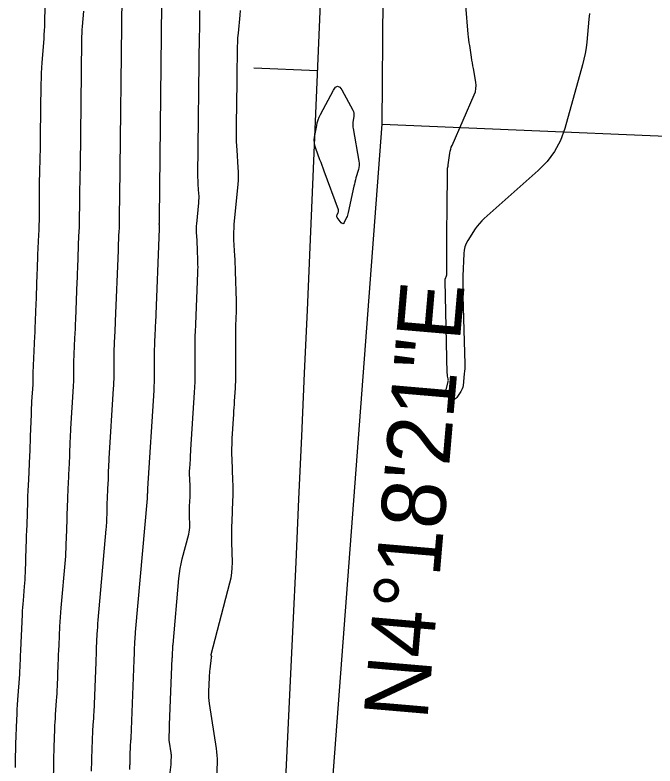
# Model space of a CAD drawing. Extents: x 1768942 to 1774819, y 723037 to 732099.
# Drawn here: x 1770550.2 to 1770610.2, y 730924.2 to 730994.7 of the extents above; entities that cross this region are included whole.
import ezdxf

# ---------------------------------------------------------------- set-up
doc = ezdxf.new("R2010")
doc.units = 0
for name, color, linetype in [('R_Contours', 7, 'Continuous'), ('R_Horz Alg', 7, 'Continuous'), ('R_Horz Alg Annot', 7, 'Continuous')]:
    doc.layers.add(name, color=color, linetype=linetype)

msp = doc.modelspace()

# ---------------------------------------------------------------- linework, layer by layer
at = {"layer": 'R_Contours'}
for points in [[(1770560.925, 730923.896), (1770560.946, 730924.309), (1770560.95, 730924.406), (1770560.954, 730924.503), (1770560.957, 730924.6), (1770560.959, 730924.697), (1770560.967, 730925.09), (1770560.969, 730925.184), (1770560.971, 730925.279), (1770560.974, 730925.373), (1770560.977, 730925.467), (1770560.991, 730925.872), (1770560.994, 730925.952), (1770560.998, 730926.032), (1770561.003, 730926.112), (1770561.008, 730926.192), (1770561.031, 730926.513), (1770561.036, 730926.593), (1770561.041, 730926.673), (1770561.045, 730926.753), (1770561.048, 730926.833), (1770561.339, 730934.168), (1770561.348, 730934.387), (1770561.357, 730934.606), (1770561.366, 730934.825), (1770561.376, 730935.044), (1770561.416, 730935.919), (1770561.427, 730936.138), (1770561.441, 730936.357), (1770561.456, 730936.575), (1770561.474, 730936.794), (1770562.586, 730949.35), (1770562.589, 730949.376), (1770562.59, 730949.402), (1770562.592, 730949.428), (1770562.593, 730949.454), (1770562.603, 730949.773), (1770562.604, 730949.8), (1770562.605, 730949.826), (1770562.607, 730949.853), (1770562.608, 730949.88), (1770562.613, 730949.993), (1770562.614, 730950.016), (1770562.615, 730950.039), (1770562.616, 730950.062), (1770562.617, 730950.085), (1770562.62, 730950.176), (1770562.621, 730950.199), (1770562.622, 730950.222), (1770562.623, 730950.245), (1770562.625, 730950.268), (1770563.21, 730959.488), (1770563.231, 730959.879), (1770563.247, 730960.271), (1770563.256, 730960.663), (1770563.258, 730961.055), (1770563.255, 730962.92), (1770563.256, 730963.164), (1770563.26, 730963.407), (1770563.267, 730963.651), (1770563.276, 730963.895), (1770563.319, 730964.869), (1770563.329, 730965.112), (1770563.34, 730965.356), (1770563.35, 730965.599), (1770563.36, 730965.843), (1770563.712, 730974.656), (1770563.713, 730974.685), (1770563.714, 730974.715), (1770563.713, 730974.744), (1770563.713, 730974.773), (1770563.708, 730974.906), (1770563.707, 730974.928), (1770563.706, 730974.95), (1770563.705, 730974.971), (1770563.704, 730974.993), (1770563.699, 730975.08), (1770563.699, 730975.102), (1770563.699, 730975.124), (1770563.699, 730975.145), (1770563.701, 730975.167), (1770563.722, 730975.386), (1770563.724, 730975.41), (1770563.724, 730975.434), (1770563.724, 730975.458), (1770563.723, 730975.482), (1770563.716, 730975.577), (1770563.715, 730975.601), (1770563.714, 730975.625), (1770563.713, 730975.649), (1770563.713, 730975.673), (1770563.981, 730998.643)], [(1770557.342, 730923.739), (1770557.362, 730924.758), (1770557.368, 730925.002), (1770557.374, 730925.246), (1770557.381, 730925.49), (1770557.389, 730925.734), (1770557.425, 730926.783), (1770557.433, 730926.991), (1770557.443, 730927.198), (1770557.455, 730927.406), (1770557.469, 730927.613), (1770557.527, 730928.442), (1770557.541, 730928.65), (1770557.553, 730928.857), (1770557.564, 730929.065), (1770557.573, 730929.272), (1770557.76, 730933.986), (1770557.773, 730934.315), (1770557.787, 730934.644), (1770557.801, 730934.974), (1770557.816, 730935.303), (1770557.876, 730936.62), (1770557.892, 730936.949), (1770557.913, 730937.278), (1770557.937, 730937.607), (1770557.964, 730937.935), (1770558.719, 730946.465), (1770558.735, 730946.654), (1770558.747, 730946.842), (1770558.758, 730947.031), (1770558.765, 730947.22), (1770558.797, 730948.164), (1770558.816, 730948.731), (1770558.842, 730949.526), (1770558.849, 730949.718), (1770558.857, 730949.91), (1770558.865, 730950.102), (1770558.874, 730950.294), (1770558.914, 730951.115), (1770558.921, 730951.28), (1770558.928, 730951.445), (1770558.935, 730951.61), (1770558.941, 730951.776), (1770558.963, 730952.437), (1770558.969, 730952.602), (1770558.977, 730952.767), (1770558.985, 730952.932), (1770558.995, 730953.097), (1770559.412, 730959.669), (1770559.428, 730959.961), (1770559.44, 730960.253), (1770559.446, 730960.545), (1770559.448, 730960.837), (1770559.446, 730962.005), (1770559.448, 730962.297), (1770559.452, 730962.589), (1770559.46, 730962.881), (1770559.471, 730963.173), (1770559.535, 730964.629), (1770559.55, 730964.969), (1770559.565, 730965.309), (1770559.579, 730965.649), (1770559.593, 730965.989), (1770559.858, 730972.625), (1770559.863, 730972.763), (1770559.868, 730972.9), (1770559.873, 730973.038), (1770559.878, 730973.175), (1770559.895, 730973.726), (1770559.9, 730973.863), (1770559.906, 730974.001), (1770559.912, 730974.138), (1770559.918, 730974.276), (1770559.946, 730974.84), (1770559.952, 730974.98), (1770559.957, 730975.12), (1770559.96, 730975.26), (1770559.961, 730975.4), (1770559.962, 730976.002), (1770559.963, 730976.141), (1770559.964, 730976.279), (1770559.967, 730976.417), (1770559.97, 730976.556), (1770559.983, 730977.109), (1770559.986, 730977.248), (1770559.989, 730977.386), (1770559.991, 730977.525), (1770559.993, 730977.663), (1770560.223, 730996.458)], [(1770552.939, 730995.548), (1770552.915, 730994.022), (1770552.906, 730993.641), (1770552.891, 730993.26), (1770552.871, 730992.879), (1770552.844, 730992.499), (1770552.672, 730990.272), (1770552.638, 730989.774), (1770552.612, 730989.275), (1770552.594, 730988.776), (1770552.583, 730988.277), (1770552.523, 730983.358), (1770552.517, 730982.903), (1770552.509, 730982.448), (1770552.5, 730981.993), (1770552.49, 730981.538), (1770552.445, 730979.719), (1770552.436, 730979.264), (1770552.428, 730978.81), (1770552.423, 730978.355), (1770552.421, 730977.9), (1770552.417, 730975.92), (1770552.413, 730975.46), (1770552.404, 730975), (1770552.389, 730974.54), (1770552.369, 730974.081), (1770552.276, 730972.226), (1770552.255, 730971.774), (1770552.235, 730971.323), (1770552.218, 730970.871), (1770552.202, 730970.419), (1770552.135, 730968.33), (1770552.125, 730968.018), (1770552.114, 730967.707), (1770552.102, 730967.395), (1770552.09, 730967.084), (1770552.04, 730965.837), (1770552.028, 730965.526), (1770552.015, 730965.214), (1770552.001, 730964.903), (1770551.988, 730964.591), (1770551.836, 730961.138), (1770551.832, 730961.046), (1770551.83, 730960.953), (1770551.828, 730960.861), (1770551.828, 730960.769), (1770551.828, 730960.401), (1770551.828, 730960.309), (1770551.826, 730960.217), (1770551.822, 730960.125), (1770551.817, 730960.033), (1770551.716, 730958.447), (1770551.699, 730958.152), (1770551.683, 730957.857), (1770551.67, 730957.562), (1770551.659, 730957.266), (1770551.588, 730955.157), (1770551.572, 730954.707), (1770551.554, 730954.257), (1770551.535, 730953.807), (1770551.514, 730953.358), (1770551.406, 730951.121), (1770551.382, 730950.599), (1770551.359, 730950.076), (1770551.339, 730949.553), (1770551.32, 730949.03), (1770551.248, 730946.867), (1770551.231, 730946.353), (1770551.213, 730945.838), (1770551.196, 730945.324), (1770551.179, 730944.809), (1770551.098, 730942.375), (1770551.084, 730942.049), (1770551.067, 730941.723), (1770551.045, 730941.397), (1770551.018, 730941.072), (1770550.903, 730939.772), (1770550.876, 730939.446), (1770550.852, 730939.121), (1770550.832, 730938.795), (1770550.816, 730938.469), (1770550.662, 730935.095), (1770550.654, 730934.908), (1770550.646, 730934.721), (1770550.638, 730934.534), (1770550.631, 730934.347), (1770550.601, 730933.599), (1770550.593, 730933.413), (1770550.583, 730933.226), (1770550.572, 730933.039), (1770550.56, 730932.852), (1770550.39, 730930.454), (1770550.359, 730929.992), (1770550.333, 730929.53), (1770550.311, 730929.068), (1770550.293, 730928.605), (1770550.212, 730926.269), (1770550.195, 730925.725), (1770550.179, 730925.181), (1770550.165, 730924.638), (1770550.154, 730924.094)], [(1770556.571, 730995.085), (1770556.46, 730993.651), (1770556.438, 730993.331), (1770556.421, 730993.01), (1770556.41, 730992.689), (1770556.403, 730992.368), (1770556.258, 730980.51), (1770556.254, 730980.214), (1770556.249, 730979.917), (1770556.243, 730979.62), (1770556.237, 730979.324), (1770556.207, 730978.137), (1770556.201, 730977.841), (1770556.196, 730977.544), (1770556.193, 730977.248), (1770556.192, 730976.951), (1770556.189, 730975.66), (1770556.186, 730975.36), (1770556.18, 730975.06), (1770556.171, 730974.76), (1770556.157, 730974.46), (1770556.097, 730973.251), (1770556.083, 730972.956), (1770556.07, 730972.662), (1770556.059, 730972.367), (1770556.049, 730972.072), (1770556.011, 730970.893), (1770556.001, 730970.598), (1770555.991, 730970.304), (1770555.98, 730970.009), (1770555.968, 730969.714), (1770555.825, 730966.134), (1770555.808, 730965.698), (1770555.789, 730965.261), (1770555.771, 730964.825), (1770555.752, 730964.389), (1770555.653, 730962.155), (1770555.646, 730961.963), (1770555.641, 730961.771), (1770555.638, 730961.579), (1770555.637, 730961.387), (1770555.638, 730960.619), (1770555.637, 730960.427), (1770555.633, 730960.235), (1770555.625, 730960.043), (1770555.615, 730959.851), (1770555.365, 730955.926), (1770555.347, 730955.619), (1770555.331, 730955.312), (1770555.317, 730955.004), (1770555.306, 730954.697), (1770555.264, 730953.466), (1770555.253, 730953.159), (1770555.241, 730952.851), (1770555.228, 730952.544), (1770555.214, 730952.236), (1770555.14, 730950.707), (1770555.123, 730950.35), (1770555.108, 730949.993), (1770555.094, 730949.635), (1770555.081, 730949.278), (1770555.032, 730947.799), (1770555.02, 730947.448), (1770555.008, 730947.096), (1770554.997, 730946.744), (1770554.985, 730946.392), (1770554.938, 730944.986), (1770554.924, 730944.634), (1770554.905, 730944.283), (1770554.881, 730943.932), (1770554.852, 730943.581), (1770554.453, 730939.077), (1770554.417, 730938.638), (1770554.385, 730938.199), (1770554.358, 730937.76), (1770554.336, 730937.321), (1770554.256, 730935.562), (1770554.236, 730935.122), (1770554.217, 730934.683), (1770554.199, 730934.243), (1770554.181, 730933.803), (1770554.098, 730931.712), (1770554.083, 730931.377), (1770554.066, 730931.042), (1770554.046, 730930.707), (1770554.024, 730930.372), (1770553.929, 730929.034), (1770553.907, 730928.699), (1770553.888, 730928.364), (1770553.872, 730928.029), (1770553.859, 730927.694), (1770553.801, 730926.002), (1770553.788, 730925.608), (1770553.776, 730925.214), (1770553.766, 730924.82), (1770553.758, 730924.426), (1770553.726, 730922.781)], [(1770564.559, 730922.366), (1770564.797, 730924.381), (1770564.806, 730924.47), (1770564.814, 730924.56), (1770564.82, 730924.65), (1770564.823, 730924.74), (1770564.835, 730925.1), (1770564.835, 730925.19), (1770564.832, 730925.28), (1770564.824, 730925.37), (1770564.813, 730925.459), (1770564.653, 730926.487), (1770564.636, 730926.62), (1770564.625, 730926.754), (1770564.621, 730926.888), (1770564.624, 730927.022), (1770564.648, 730927.56), (1770564.653, 730927.694), (1770564.659, 730927.829), (1770564.665, 730927.963), (1770564.67, 730928.098), (1770564.918, 730934.351), (1770564.922, 730934.459), (1770564.927, 730934.568), (1770564.932, 730934.676), (1770564.936, 730934.785), (1770564.956, 730935.219), (1770564.962, 730935.327), (1770564.968, 730935.435), (1770564.976, 730935.544), (1770564.985, 730935.652), (1770565.533, 730941.837), (1770565.584, 730942.304), (1770565.655, 730942.767), (1770565.745, 730943.227), (1770565.854, 730943.683), (1770566.459, 730945.984), (1770566.507, 730946.198), (1770566.54, 730946.414), (1770566.557, 730946.632), (1770566.56, 730946.851), (1770566.539, 730947.733), (1770566.535, 730947.953), (1770566.535, 730948.174), (1770566.539, 730948.394), (1770566.546, 730948.614), (1770566.583, 730949.499), (1770566.59, 730949.719), (1770566.592, 730949.94), (1770566.59, 730950.161), (1770566.584, 730950.382), (1770566.549, 730951.28), (1770566.543, 730951.501), (1770566.543, 730951.722), (1770566.548, 730951.943), (1770566.558, 730952.164), (1770566.612, 730953.047), (1770566.625, 730953.268), (1770566.639, 730953.489), (1770566.652, 730953.709), (1770566.666, 730953.93), (1770567.007, 730959.306), (1770567.035, 730959.797), (1770567.054, 730960.289), (1770567.065, 730960.78), (1770567.068, 730961.273), (1770567.064, 730963.931), (1770567.065, 730964.078), (1770567.067, 730964.225), (1770567.071, 730964.373), (1770567.076, 730964.52), (1770567.102, 730965.109), (1770567.109, 730965.256), (1770567.115, 730965.403), (1770567.121, 730965.55), (1770567.127, 730965.698), (1770567.32, 730970.532), (1770567.329, 730970.796), (1770567.332, 730971.06), (1770567.33, 730971.324), (1770567.323, 730971.588), (1770567.282, 730972.782), (1770567.275, 730972.977), (1770567.267, 730973.173), (1770567.257, 730973.369), (1770567.247, 730973.565), (1770567.204, 730974.347), (1770567.197, 730974.543), (1770567.198, 730974.738), (1770567.205, 730974.933), (1770567.22, 730975.129), (1770567.406, 730977.096), (1770567.422, 730977.31), (1770567.429, 730977.525), (1770567.427, 730977.74), (1770567.417, 730977.954), (1770567.356, 730978.814), (1770567.343, 730979.029), (1770567.334, 730979.244), (1770567.33, 730979.459), (1770567.33, 730979.675), (1770567.485, 730992.917), (1770567.488, 730993.188), (1770567.491, 730993.459), (1770567.494, 730993.729), (1770567.497, 730994), (1770567.509, 730995.16)], [(1770569.107, 730923.234), (1770569.148, 730924.566), (1770569.151, 730924.898), (1770569.138, 730925.23), (1770569.11, 730925.56), (1770569.067, 730925.89), (1770568.412, 730930.113), (1770568.376, 730930.393), (1770568.354, 730930.674), (1770568.345, 730930.956), (1770568.351, 730931.238), (1770568.409, 730932.556), (1770568.419, 730932.746), (1770568.433, 730932.935), (1770568.45, 730933.125), (1770568.472, 730933.314), (1770568.606, 730934.425), (1770568.609, 730934.448), (1770568.611, 730934.47), (1770568.616, 730934.515), (1770568.616, 730934.526), (1770568.615, 730934.537), (1770568.612, 730934.548), (1770568.608, 730934.558), (1770568.573, 730934.635), (1770568.567, 730934.651), (1770568.564, 730934.668), (1770568.565, 730934.685), (1770568.568, 730934.702), (1770570.332, 730941.421), (1770570.437, 730941.891), (1770570.51, 730942.364), (1770570.548, 730942.841), (1770570.554, 730943.322), (1770570.507, 730945.255), (1770570.499, 730945.738), (1770570.499, 730946.22), (1770570.508, 730946.703), (1770570.524, 730947.186), (1770570.604, 730949.124), (1770570.619, 730949.608), (1770570.625, 730950.091), (1770570.62, 730950.575), (1770570.607, 730951.059), (1770570.53, 730953.029), (1770570.517, 730953.513), (1770570.516, 730953.997), (1770570.527, 730954.481), (1770570.55, 730954.965), (1770570.689, 730957.258), (1770570.707, 730957.563), (1770570.726, 730957.868), (1770570.745, 730958.173), (1770570.764, 730958.478), (1770570.841, 730959.697), (1770570.858, 730960.001), (1770570.87, 730960.306), (1770570.877, 730960.612), (1770570.879, 730960.917), (1770570.873, 730964.942), (1770570.873, 730964.992), (1770570.874, 730965.043), (1770570.875, 730965.094), (1770570.877, 730965.145), (1770570.886, 730965.349), (1770570.888, 730965.4), (1770570.89, 730965.45), (1770570.892, 730965.501), (1770570.894, 730965.552), (1770570.949, 730966.916), (1770570.956, 730967.161), (1770570.959, 730967.405), (1770570.958, 730967.65), (1770570.952, 730967.894), (1770570.856, 730970.657), (1770570.842, 730971.027), (1770570.827, 730971.397), (1770570.809, 730971.766), (1770570.79, 730972.136), (1770570.709, 730973.614), (1770570.696, 730973.983), (1770570.697, 730974.352), (1770570.711, 730974.721), (1770570.739, 730975.09), (1770571.091, 730978.805), (1770571.121, 730979.21), (1770571.134, 730979.616), (1770571.131, 730980.021), (1770571.11, 730980.427), (1770570.995, 730982.051), (1770570.971, 730982.457), (1770570.955, 730982.863), (1770570.947, 730983.27), (1770570.947, 730983.676), (1770570.988, 730987.192), (1770570.994, 730987.689), (1770571, 730988.187), (1770571.005, 730988.684), (1770571.01, 730989.182), (1770571.032, 730991.312), (1770571.041, 730991.739), (1770571.058, 730992.165), (1770571.084, 730992.591), (1770571.119, 730993.017), (1770571.275, 730994.718), (1770571.31, 730995.144)], [(1770604.096, 730994.871), (1770604.024, 730994.337), (1770603.818, 730992.182), (1770603.754, 730991.645), (1770603.668, 730991.112), (1770603.557, 730990.584), (1770603.424, 730990.061), (1770601.753, 730984.078), (1770601.353, 730982.953), (1770600.807, 730981.919), (1770600.116, 730980.976), (1770599.278, 730980.125), (1770594.201, 730975.633), (1770593.965, 730975.41), (1770593.746, 730975.171), (1770593.545, 730974.918), (1770593.361, 730974.649), (1770592.659, 730973.547), (1770592.504, 730973.265), (1770592.39, 730972.97), (1770592.316, 730972.663), (1770592.283, 730972.343), (1770592.2, 730970.199), (1770592.186, 730969.733), (1770592.18, 730969.267), (1770592.181, 730968.801), (1770592.19, 730968.335), (1770592.368, 730961.996), (1770592.37, 730961.76), (1770592.365, 730961.523), (1770592.351, 730961.288), (1770592.33, 730961.052), (1770592.211, 730959.958), (1770592.184, 730959.802), (1770592.14, 730959.652), (1770592.078, 730959.509), (1770591.998, 730959.373), (1770591.623, 730958.812), (1770591.539, 730958.719), (1770591.446, 730958.677), (1770591.345, 730958.686), (1770591.235, 730958.747), (1770590.776, 730959.095), (1770590.681, 730959.189), (1770590.622, 730959.295), (1770590.601, 730959.415), (1770590.618, 730959.548), (1770590.815, 730960.334), (1770590.827, 730960.396), (1770590.832, 730960.458), (1770590.83, 730960.521), (1770590.82, 730960.584), (1770590.766, 730960.834), (1770590.754, 730960.897), (1770590.745, 730960.96), (1770590.739, 730961.024), (1770590.736, 730961.088), (1770590.519, 730969.789), (1770590.521, 730969.845), (1770590.528, 730969.9), (1770590.541, 730969.953), (1770590.559, 730970.006), (1770590.662, 730970.256), (1770590.673, 730970.288), (1770590.681, 730970.321), (1770590.685, 730970.355), (1770590.685, 730970.389), (1770590.677, 730970.527), (1770590.676, 730970.561), (1770590.675, 730970.596), (1770590.674, 730970.63), (1770590.674, 730970.665), (1770590.694, 730974.042), (1770590.698, 730974.616), (1770590.702, 730975.191), (1770590.706, 730975.765), (1770590.71, 730976.34), (1770590.74, 730980.21), (1770590.742, 730980.245), (1770590.746, 730980.28), (1770590.752, 730980.314), (1770590.76, 730980.348), (1770590.812, 730980.527), (1770590.815, 730980.539), (1770590.816, 730980.552), (1770590.816, 730980.564), (1770590.815, 730980.576), (1770590.806, 730980.626), (1770590.804, 730980.639), (1770590.803, 730980.651), (1770590.804, 730980.664), (1770590.805, 730980.676), (1770590.971, 730981.773), (1770591.005, 730981.958), (1770591.051, 730982.139), (1770591.109, 730982.318), (1770591.179, 730982.492), (1770593.263, 730987.241), (1770593.365, 730987.526), (1770593.422, 730987.816), (1770593.436, 730988.111), (1770593.405, 730988.412), (1770593.181, 730989.695), (1770593.135, 730989.964), (1770593.09, 730990.234), (1770593.047, 730990.504), (1770593.004, 730990.774), (1770592.837, 730991.854), (1770592.797, 730992.124), (1770592.762, 730992.395), (1770592.731, 730992.666), (1770592.705, 730992.938), (1770592.467, 730995.636)]]:
    msp.add_lwpolyline(points, dxfattribs=at)
msp.add_lwpolyline([(1770581.925, 730985.658), (1770581.961, 730985.521), (1770581.974, 730985.38), (1770581.963, 730985.235), (1770581.875, 730984.648), (1770581.859, 730984.501), (1770581.854, 730984.354), (1770581.862, 730984.208), (1770581.882, 730984.062), (1770582.426, 730981.007), (1770582.45, 730980.808), (1770582.452, 730980.61), (1770582.43, 730980.414), (1770582.385, 730980.218), (1770582.161, 730979.439), (1770582.107, 730979.244), (1770582.056, 730979.048), (1770582.008, 730978.85), (1770581.964, 730978.653), (1770581.44, 730976.189), (1770581.41, 730976.065), (1770581.372, 730975.944), (1770581.327, 730975.826), (1770581.275, 730975.71), (1770581.05, 730975.25), (1770580.992, 730975.163), (1770580.928, 730975.129), (1770580.859, 730975.15), (1770580.785, 730975.225), (1770580.406, 730975.727), (1770580.374, 730975.782), (1770580.359, 730975.839), (1770580.363, 730975.898), (1770580.383, 730975.958), (1770580.502, 730976.203), (1770580.525, 730976.264), (1770580.534, 730976.326), (1770580.531, 730976.389), (1770580.514, 730976.452), (1770579.177, 730980.082), (1770579.079, 730980.347), (1770578.981, 730980.611), (1770578.882, 730980.875), (1770578.782, 730981.139), (1770578.378, 730982.206), (1770578.299, 730982.466), (1770578.256, 730982.729), (1770578.249, 730982.996), (1770578.279, 730983.266), (1770578.473, 730984.354), (1770578.531, 730984.622), (1770578.61, 730984.883), (1770578.709, 730985.138), (1770578.828, 730985.385), (1770580.051, 730987.689), (1770580.244, 730987.962), (1770580.438, 730988.053), (1770580.633, 730987.964), (1770580.829, 730987.694), (1770581.866, 730985.79)], close=True, dxfattribs=at)
at = {"layer": 'R_Horz Alg'}
for p, q in [((1770584.608, 730984.478), (1770588.048, 731363.138)), ((1770556.177, 730606.87), (1770584.608, 730984.478))]:
    msp.add_line(p, q, dxfattribs=at)
for points in [[(1770572.564, 730989.775), (1770578.559, 730989.525)], [(1770584.608, 730984.478), (1770704.502, 730979.425)], [(1770584.608, 730984.478), (1770704.502, 730979.425)]]:
    msp.add_lwpolyline(points, dxfattribs=at)
msp.add_arc((1759129.36, 731467.219), 11459.16, 355.6942048, 359.4795914, dxfattribs=at)

# ---------------------------------------------------------------- texts
at = {"layer": 'R_Horz Alg Annot'}
msp.add_text('N4%%d18\'21"E', height=6, rotation=85.08386, dxfattribs=at).set_placement((1770588.85, 730928.473))

doc.saveas('drawing.dxf')
